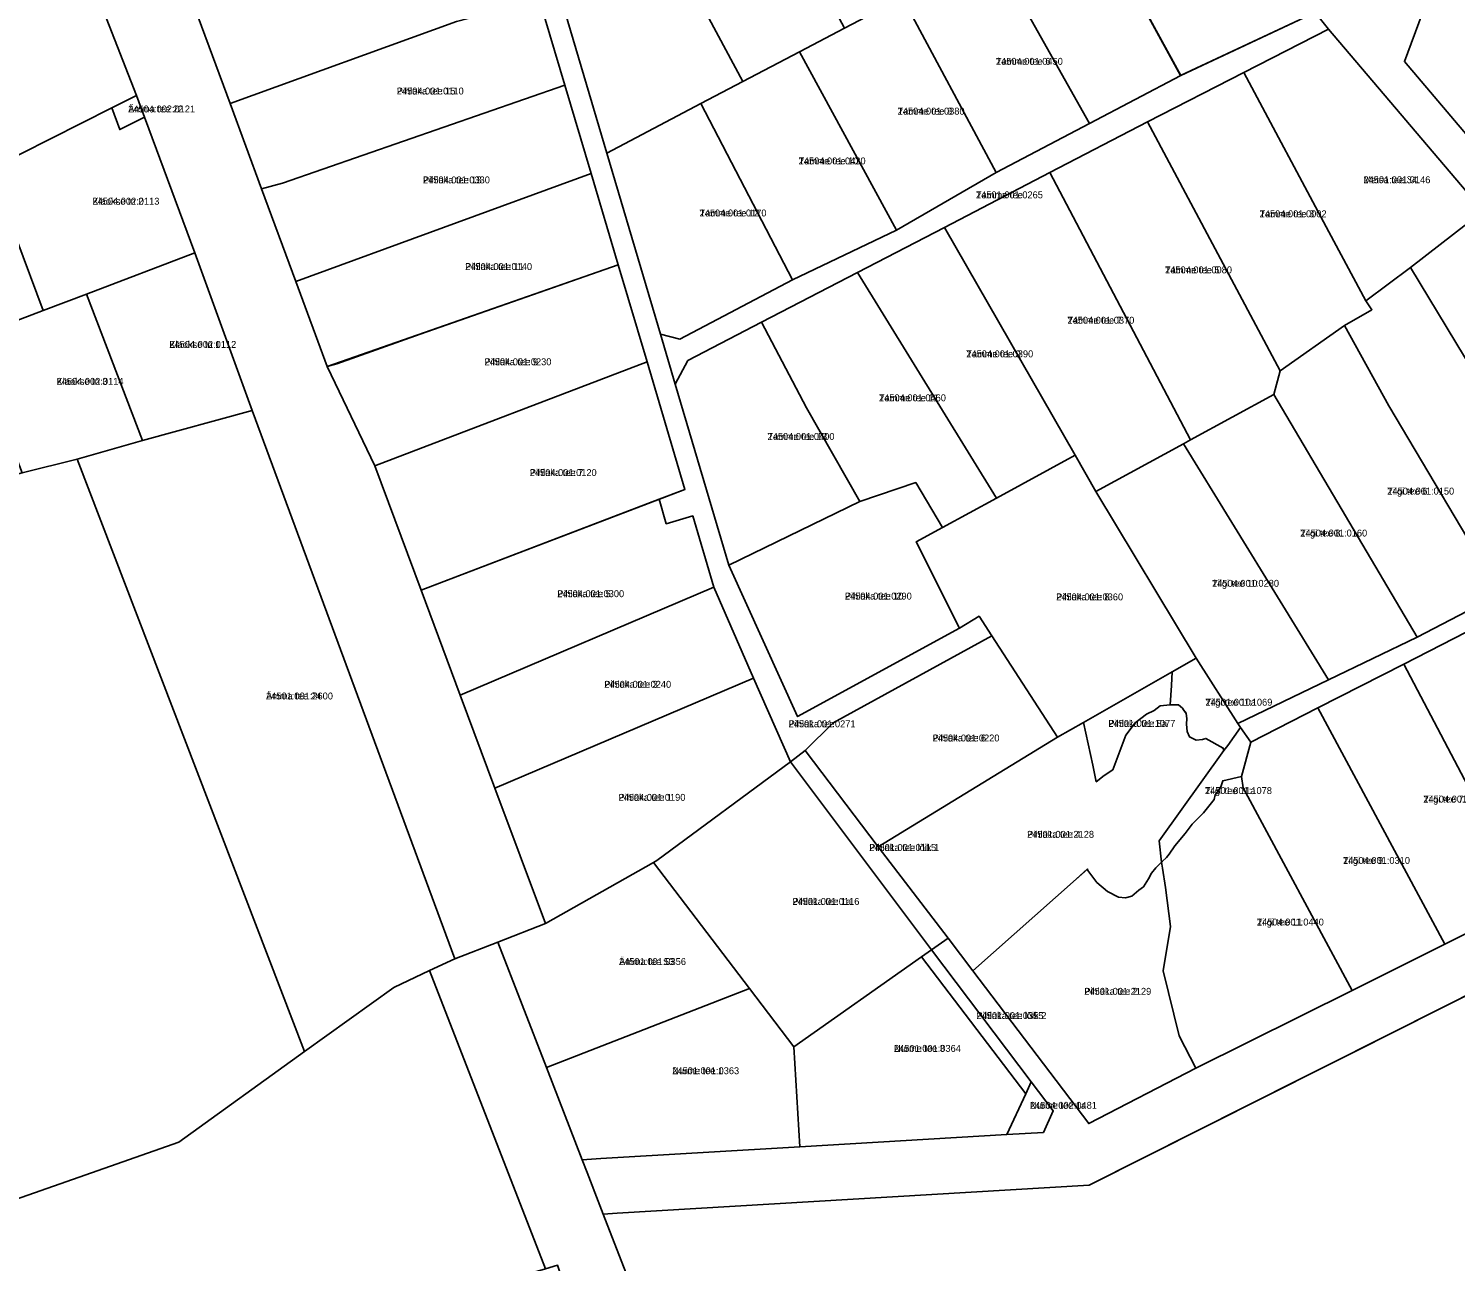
# Model space of a CAD drawing. Extents: x 551291 to 575799, y 6581704 to 6610137.
# Drawn here: x 551707.6 to 552016.8, y 6590972.2 to 6591239.3 of the extents above; entities that cross this region are included whole.
import ezdxf

# ---------------------------------------------------------------- set-up
doc = ezdxf.new("R2010")
doc.units = 0
for name, color, linetype in [('L_AADRESS', 7, 'Continuous'), ('PIIR', 7, 'Continuous'), ('TUNNUS', 7, 'Continuous')]:
    doc.layers.add(name, color=color, linetype=linetype)

msp = doc.modelspace()

# ---------------------------------------------------------------- linework, layer by layer
at = {"layer": 'PIIR'}
for points in [[(551701.29, 6591351.43), (551712.87, 6591319.4), (551715.45, 6591320.33), (551724.64, 6591295.4), (551734.51, 6591268.62), (551744.41, 6591241.79), (551751.32, 6591223.06), (551758.13, 6591204.61), (551765.54, 6591184.52), (551772.34, 6591166.09), (551782.64, 6591144.59), (551792.69, 6591117.63), (551801.16, 6591094.92), (551808.64, 6591074.74), (551819.62, 6591045.45), (551809.29, 6591041.41), (551800.02, 6591037.82), (551756.11, 6591156.6), (551743.63, 6591190.71), (551732.76, 6591220.16), (551731.03, 6591224.85), (551697.08, 6591311.6)], [(551821.21, 6591251.88), (551832.93, 6591212.34), (551844.57, 6591173.08), (551847.77, 6591162.31), (551859.38, 6591123.09), (551874.27, 6591090.27), (551909.33, 6591109.44), (551913.61, 6591112.01), (551916.35, 6591107.73), (551881.97, 6591088.88), (551875.88, 6591082.91), (551872.7, 6591080.47), (551864.73, 6591098.59), (551856.15, 6591118.28), (551851.55, 6591133.75), (551845.8, 6591132.04), (551844.24, 6591137.36), (551849.84, 6591139.5), (551841.64, 6591167.12), (551835.39, 6591188.16), (551829.52, 6591207.93), (551823.84, 6591227.04), (551818.36, 6591245.46)], [(552041.41, 6591041.02), (551994.68, 6591017.51), (551983.25, 6591011.76), (551937.47, 6590988.73), (551835.16, 6590982.69), (551832.17, 6590982.51), (551831.44, 6590984.38), (551828.69, 6590991.47), (551827.6, 6590994.26), (551831.6, 6590994.5), (551874.74, 6590997.05), (551919.58, 6590999.71), (551927.52, 6591000.16), (551929.68, 6591004.83), (551924.89, 6591011.17), (551903.3, 6591039.74), (551906.87, 6591042.28), (551912.23, 6591035.19), (551937.34, 6591002.11), (551960.57, 6591014.09), (551994.47, 6591030.95), (552014.5, 6591041), (552032.69, 6591050.15)]]:
    msp.add_lwpolyline(points, dxfattribs=at)
for points in [[(551592.26, 6591318.17), (551621.99, 6591332.29), (551623.99, 6591329.04), (551632.52, 6591311.28), (551638.82, 6591301.29), (551648.47, 6591293.24), (551660.58, 6591291.58), (551671.63, 6591296.03), (551697.08, 6591311.6), (551731.03, 6591224.85), (551725.67, 6591222.15), (551699.31, 6591208.85), (551670.73, 6591194.44), (551633.68, 6591175.75), (551582.09, 6591146.82), (551586.14, 6591107.57), (551562.34, 6591100.09), (551552.1, 6591119.71), (551549.82, 6591157.52), (551565.91, 6591305.65), (551578.48, 6591311.61)], [(552005.77, 6591232.17), (552015.83, 6591259.33), (552088.53, 6591298.69), (552112.37, 6591206.21), (552049.91, 6591174.23), (552042.31, 6591189.1)], [(551744.41, 6591241.79), (551781.76, 6591257.73), (551796, 6591268.19), (551802.72, 6591274.63), (551806.37, 6591277.83), (551819.04, 6591259.7), (551817.04, 6591252.23), (551818.36, 6591245.46), (551800.32, 6591240.84), (551751.32, 6591223.06)], [(551841.89, 6591266.09), (551864.01, 6591277.78), (551884.41, 6591239.44), (551874.65, 6591234.3), (551862.38, 6591227.84)], [(551936.63, 6591266.94), (551956.64, 6591277.45), (551986.13, 6591243.2), (551986.45, 6591242.8), (551957.26, 6591229.16)], [(551821.21, 6591251.88), (551822.78, 6591256), (551841.89, 6591266.09), (551862.38, 6591227.84), (551853.31, 6591223.07), (551832.93, 6591212.34)], [(551928.43, 6591262.61), (551936.66, 6591266.94), (551957.29, 6591229.16), (551937.5, 6591218.74), (551916.4, 6591256.28)], [(551986.45, 6591242.8), (551986.13, 6591243.2), (552010.61, 6591256.5), (552015.83, 6591259.33), (552005.77, 6591232.17), (552042.31, 6591189.1), (552049.91, 6591174.23), (552072.65, 6591129.71), (552065.53, 6591126.08), (552063.05, 6591130.94), (552061.12, 6591134.72), (552035.62, 6591184.65), (552022.81, 6591199.75), (551989.34, 6591239.21)], [(551906.25, 6591250.94), (551916.4, 6591256.28), (551937.5, 6591218.74), (551917.26, 6591208.12), (551896.98, 6591246.06)], [(551800.32, 6591240.84), (551818.36, 6591245.46), (551823.84, 6591227.04), (551762.65, 6591205.81), (551758.13, 6591204.61), (551751.32, 6591223.06)], [(551874.65, 6591234.3), (551884.41, 6591239.44), (551896.98, 6591246.06), (551917.26, 6591208.12), (551895.69, 6591195.68)], [(551986.45, 6591242.8), (551989.34, 6591239.21), (551970.94, 6591229.81), (551950.07, 6591219.1), (551928.94, 6591208.12), (551906.07, 6591196.24), (551887.24, 6591186.46), (551866.46, 6591175.69), (551850.49, 6591167.41), (551847.77, 6591162.31), (551844.57, 6591173.08), (551848.73, 6591172.06), (551873.13, 6591184.9), (551895.69, 6591195.68), (551917.26, 6591208.12), (551937.5, 6591218.74), (551957.29, 6591229.16)], [(551970.94, 6591229.81), (551989.34, 6591239.21), (552022.81, 6591199.75), (552007.11, 6591187.53), (551997.39, 6591180.36), (551989.4, 6591195.28)], [(551862.38, 6591227.84), (551874.65, 6591234.3), (551895.69, 6591195.68), (551873.13, 6591184.9), (551853.31, 6591223.07)], [(551970.94, 6591229.81), (551989.4, 6591195.28), (551997.39, 6591180.36), (551998.71, 6591178.42), (551992.78, 6591174.99), (551978.84, 6591165.19), (551950.07, 6591219.1)], [(551758.13, 6591204.61), (551762.65, 6591205.81), (551823.84, 6591227.04), (551829.52, 6591207.93), (551765.54, 6591184.52)], [(551725.67, 6591222.15), (551731.03, 6591224.85), (551732.76, 6591220.16), (551727.38, 6591217.45)], [(551853.31, 6591223.07), (551873.13, 6591184.9), (551848.73, 6591172.06), (551844.57, 6591173.08), (551832.93, 6591212.34)], [(551699.31, 6591208.85), (551725.67, 6591222.15), (551727.38, 6591217.45), (551732.76, 6591220.16), (551743.63, 6591190.71), (551720.15, 6591181.8), (551710.76, 6591178.24)], [(551950.07, 6591219.1), (551978.84, 6591165.19), (551977.46, 6591160.07), (551959.38, 6591150.2), (551928.94, 6591208.12)], [(551670.73, 6591194.44), (551699.31, 6591208.85), (551710.76, 6591178.24), (551695.02, 6591172.27), (551681, 6591166.95)], [(551829.52, 6591207.93), (551835.39, 6591188.16), (551792.49, 6591173.14), (551774.39, 6591166.71), (551772.34, 6591166.09), (551765.54, 6591184.52)], [(551957.88, 6591149.38), (551938.87, 6591139), (551934.41, 6591146.9), (551906.07, 6591196.24), (551928.94, 6591208.12), (551959.38, 6591150.2)], [(552022.81, 6591199.75), (552035.58, 6591184.65), (552061.12, 6591134.72), (552044.26, 6591126.06), (552007.11, 6591187.53)], [(551934.41, 6591146.9), (551917.37, 6591137.62), (551887.24, 6591186.46), (551906.07, 6591196.24)], [(551720.15, 6591181.8), (551743.63, 6591190.71), (551756.11, 6591156.6), (551732.35, 6591150.09)], [(551772.34, 6591166.09), (551835.39, 6591188.16), (551841.64, 6591167.12), (551782.64, 6591144.59)], [(551887.24, 6591186.46), (551917.37, 6591137.62), (551905.68, 6591131.26), (551899.87, 6591140.98), (551887.73, 6591136.87), (551876.21, 6591157.13), (551866.46, 6591175.69)], [(551992.78, 6591174.99), (551998.71, 6591178.42), (551997.39, 6591180.36), (552007.11, 6591187.53), (552044.26, 6591126.06), (552026.61, 6591116.88), (552002.4, 6591157.62)], [(551706.24, 6591143.05), (551695.02, 6591172.27), (551710.76, 6591178.24), (551720.15, 6591181.8), (551732.35, 6591150.09), (551718.14, 6591146.05)], [(551847.77, 6591162.31), (551850.49, 6591167.41), (551866.46, 6591175.69), (551876.21, 6591157.13), (551887.73, 6591136.87), (551859.38, 6591123.09)], [(551978.84, 6591165.19), (551992.78, 6591174.99), (552002.4, 6591157.62), (552026.61, 6591116.88), (552008.49, 6591107.5), (551977.46, 6591160.07)], [(551841.64, 6591167.12), (551849.84, 6591139.5), (551792.69, 6591117.63), (551782.64, 6591144.59)], [(551959.38, 6591150.2), (551977.46, 6591160.07), (552008.49, 6591107.5), (551989.3, 6591098.24), (551957.88, 6591149.38)], [(551767.4, 6591017.71), (551718.14, 6591146.05), (551732.35, 6591150.09), (551756.11, 6591156.6), (551800.02, 6591037.82), (551794.54, 6591035.23), (551786.76, 6591031.59)], [(551969.66, 6591088.77), (551960.61, 6591102.94), (551938.87, 6591139), (551957.88, 6591149.38), (551989.3, 6591098.24)], [(551568.89, 6591090.56), (551562.34, 6591100.09), (551586.14, 6591107.57), (551638.15, 6591124.7), (551676.44, 6591134.9), (551706.24, 6591143.05), (551718.14, 6591146.05), (551767.4, 6591017.71), (551740.16, 6590998.04), (551718.56, 6590990.49), (551690.68, 6590980.77), (551688.64, 6590987.27), (551678.52, 6591009.23), (551660.89, 6591023.42), (551605.18, 6591058.47)], [(551905.68, 6591131.26), (551917.37, 6591137.62), (551934.41, 6591146.9), (551938.87, 6591139), (551960.61, 6591102.94), (551955.45, 6591099.93), (551936.25, 6591088.99), (551930.6, 6591085.78), (551916.35, 6591107.73), (551913.61, 6591112.01), (551909.33, 6591109.44), (551899.99, 6591128.16)], [(551887.73, 6591136.87), (551899.87, 6591140.98), (551905.68, 6591131.26), (551899.99, 6591128.16), (551909.33, 6591109.44), (551874.27, 6591090.27), (551859.38, 6591123.09)], [(551792.69, 6591117.63), (551844.24, 6591137.36), (551845.8, 6591132.04), (551851.55, 6591133.75), (551856.15, 6591118.28), (551801.16, 6591094.92)], [(552061.12, 6591134.72), (552063.05, 6591130.94), (552042.3, 6591120.38), (552024.6, 6591111.34), (552005.65, 6591101.66), (551987.03, 6591092.17), (551972.46, 6591084.75), (551970.25, 6591087.91), (551969.66, 6591088.77), (551989.3, 6591098.24), (552008.49, 6591107.5), (552026.61, 6591116.88), (552044.26, 6591126.06)], [(551864.73, 6591098.59), (551808.64, 6591074.74), (551801.16, 6591094.92), (551856.15, 6591118.28)], [(552024.6, 6591111.34), (552053.16, 6591060.44), (552032.69, 6591050.15), (552005.65, 6591101.66)], [(551875.88, 6591082.91), (551881.97, 6591088.88), (551916.35, 6591107.73), (551930.6, 6591085.78), (551891.7, 6591062.04)], [(551961.98, 6591085.28), (551960.64, 6591085.18), (551959.21, 6591085.86), (551958.69, 6591087.04), (551958.53, 6591088.64), (551958.58, 6591089.85), (551958.49, 6591090.97), (551957.92, 6591091.72), (551957.64, 6591092.1), (551956.83, 6591092.82), (551955.03, 6591092.82), (551955.3, 6591097.03), (551955.45, 6591099.93), (551960.61, 6591102.94), (551969.66, 6591088.77), (551970.25, 6591087.91), (551967.46, 6591084.03), (551966.66, 6591082.9), (551966.5, 6591083.43), (551962.74, 6591085.54)], [(551945.41, 6591086.24), (551942.54, 6591078.75), (551940.71, 6591077.53), (551938.98, 6591076.14), (551938.22, 6591079.71), (551936.25, 6591088.99), (551955.45, 6591099.93), (551955.3, 6591097.03), (551955.03, 6591092.82), (551952.81, 6591092.59), (551951.5, 6591091.6), (551949.9, 6591090.81), (551947.43, 6591088.9)], [(552014.5, 6591041), (551987.03, 6591092.17), (552005.65, 6591101.66), (552032.69, 6591050.15)], [(551819.62, 6591045.45), (551808.64, 6591074.74), (551864.73, 6591098.59), (551872.7, 6591080.47), (551843.78, 6591059.11), (551843.01, 6591058.64)], [(551906.87, 6591042.28), (551891.7, 6591062.04), (551930.6, 6591085.78), (551936.25, 6591088.99), (551938.22, 6591079.71), (551938.98, 6591076.14), (551940.71, 6591077.53), (551942.54, 6591078.75), (551945.41, 6591086.24), (551947.43, 6591088.9), (551949.9, 6591090.81), (551951.5, 6591091.6), (551952.81, 6591092.59), (551955.03, 6591092.82), (551956.83, 6591092.82), (551957.64, 6591092.1), (551957.92, 6591091.72), (551958.49, 6591090.98), (551958.58, 6591089.85), (551958.53, 6591088.64), (551958.69, 6591087.04), (551959.21, 6591085.85), (551960.64, 6591085.18), (551961.98, 6591085.28), (551962.74, 6591085.54), (551966.5, 6591083.43), (551966.66, 6591082.9), (551952.63, 6591063.37), (551953.13, 6591058.71), (551951.92, 6591057.52), (551950.98, 6591056.36), (551950.31, 6591055.12), (551949.22, 6591053.39), (551948.2, 6591052.63), (551946.71, 6591051.38), (551945.34, 6591050.97), (551943.8, 6591051.15), (551941.45, 6591052.36), (551939.12, 6591054.33), (551937.14, 6591056.89), (551937.08, 6591057.26), (551934.6, 6591055.05), (551912.23, 6591035.19)], [(551970.43, 6591077.27), (551972.46, 6591084.75), (551987.03, 6591092.17), (552014.5, 6591041), (551994.47, 6591030.95), (551970.83, 6591074.86)], [(551954.21, 6591059.76), (551953.28, 6591058.85), (551953.24, 6591058.82), (551953.13, 6591058.71), (551952.63, 6591063.37), (551966.66, 6591082.9), (551967.46, 6591084.03), (551970.25, 6591087.91), (551972.46, 6591084.75), (551970.43, 6591077.27), (551966.41, 6591076.36), (551965.95, 6591075.03), (551965.28, 6591073.99), (551964.74, 6591073.32), (551964.56, 6591072.33), (551962.23, 6591069.39), (551959.75, 6591066.99), (551958.22, 6591064.93), (551956.01, 6591062.28), (551954.75, 6591060.44)], [(551843.78, 6591059.11), (551872.7, 6591080.47), (551903.3, 6591039.74), (551901.15, 6591038.23), (551873.44, 6591018.71), (551863.83, 6591031.34), (551843.01, 6591058.64)], [(551872.7, 6591080.47), (551875.88, 6591082.91), (551891.7, 6591062.04), (551906.87, 6591042.28), (551903.3, 6591039.74)], [(551970.83, 6591074.86), (551994.47, 6591030.95), (551960.57, 6591014.09), (551956.96, 6591021.08), (551953.51, 6591035.17), (551955.04, 6591044.76), (551953.96, 6591053.25), (551953.35, 6591057.4), (551953.13, 6591058.71), (551953.24, 6591058.82), (551953.28, 6591058.85), (551954.21, 6591059.76), (551954.75, 6591060.44), (551956.01, 6591062.28), (551958.22, 6591064.93), (551959.75, 6591066.99), (551962.23, 6591069.39), (551964.56, 6591072.33), (551964.74, 6591073.32), (551965.28, 6591073.99), (551965.95, 6591075.03), (551966.41, 6591076.36), (551970.43, 6591077.27)], [(551819.84, 6591014.26), (551809.29, 6591041.41), (551819.62, 6591045.45), (551843.01, 6591058.64), (551863.83, 6591031.34)], [(551953.13, 6591058.71), (551953.35, 6591057.4), (551953.96, 6591053.25), (551955.04, 6591044.76), (551953.51, 6591035.17), (551956.96, 6591021.08), (551960.57, 6591014.09), (551937.34, 6591002.11), (551912.23, 6591035.19), (551934.6, 6591055.05), (551937.08, 6591057.25), (551937.14, 6591056.89), (551939.12, 6591054.33), (551941.45, 6591052.36), (551943.8, 6591051.15), (551945.34, 6591050.97), (551946.71, 6591051.38), (551948.2, 6591052.63), (551949.22, 6591053.39), (551950.31, 6591055.12), (551950.98, 6591056.36), (551951.92, 6591057.52)], [(551832.17, 6590982.51), (551835.16, 6590982.69), (551937.47, 6590988.73), (552052.66, 6591046.68), (552056.48, 6591022.45), (552064.27, 6590973.05), (552072.83, 6590918.72), (552081.4, 6590864.38), (552088.59, 6590818.77), (552089.5, 6590812.94), (551918.6, 6590788.49), (551886.69, 6590842.14)], [(551794.54, 6591035.23), (551800.02, 6591037.82), (551809.29, 6591041.41), (551819.84, 6591014.26), (551827.6, 6590994.26), (551828.69, 6590991.47), (551831.44, 6590984.38), (551832.17, 6590982.51), (551886.69, 6590842.14), (551918.6, 6590788.49), (551924.85, 6590777.97), (551903.02, 6590774.88), (551901.43, 6590786.05), (551889.25, 6590806.53), (551872.82, 6590834.16), (551872.26, 6590835.1), (551869, 6590843.49), (551856.98, 6590874.44), (551847.31, 6590899.33), (551837.58, 6590924.39), (551822.99, 6590961.96), (551825.13, 6590962.55), (551822.27, 6590971.41), (551819.61, 6590970.63)], [(551874.74, 6590997.05), (551873.44, 6591018.71), (551901.15, 6591038.23), (551923.7, 6591008.56), (551919.58, 6590999.71)], [(551923.7, 6591008.56), (551901.15, 6591038.23), (551903.3, 6591039.74), (551924.91, 6591011.16)], [(551698.09, 6590955.05), (551690.68, 6590980.77), (551718.56, 6590990.49), (551740.16, 6590998.04), (551767.4, 6591017.71), (551786.76, 6591031.59), (551794.54, 6591035.23), (551819.61, 6590970.63), (551815.16, 6590969.32), (551797.8, 6590962.57), (551787.92, 6590905.1), (551782.6, 6590874.19), (551777.32, 6590843.5), (551770.75, 6590805.28), (551767.78, 6590787.98), (551772.28, 6590756.35), (551710.96, 6590747.66), (551655.02, 6590739.72), (551623.91, 6590735.04), (551640.06, 6590768.98), (551673.7, 6590805.26), (551693.9, 6590853.77), (551696.13, 6590876.83)], [(551827.6, 6590994.26), (551819.84, 6591014.26), (551863.83, 6591031.34), (551873.44, 6591018.71), (551874.74, 6590997.05), (551831.6, 6590994.5)], [(551919.58, 6590999.71), (551923.7, 6591008.56), (551924.89, 6591011.17), (551929.68, 6591004.83), (551927.52, 6591000.16)]]:
    msp.add_lwpolyline(points, close=True, dxfattribs=at)

# ---------------------------------------------------------------- texts
at = {"layer": 'L_AADRESS'}
for s, p in [('Tamme tee 6', (551917.24, 6591231.47)), ('Pihlaka tee 15', (551787.41, 6591225.04)), ('Ämma tee 22', (551729.21, 6591221.15)), ('Tamme tee 8', (551895.95, 6591220.68)), ('Tamme tee 10', (551874.5, 6591209.89)), ('Pihlaka tee 13', (551793.09, 6591205.78)), ('Metsa tee 34', (551996.88, 6591205.82)), ('Tamme tee', (551912.92, 6591202.55)), ('Klaokse tn 2', (551721.47, 6591201.17)), ('Tamme tee 12', (551853.03, 6591198.62)), ('Tamme tee 3', (551974.39, 6591198.44)), ('Pihlaka tee 11', (551802.23, 6591187.01)), ('Tamme tee 5', (551953.89, 6591186.29)), ('Tamme tee 7', (551932.73, 6591175.38)), ('Klaokse tn 1', (551738.13, 6591170.15)), ('Pihlaka tee 9', (551806.42, 6591166.38)), ('Tamme tee 9', (551910.82, 6591168.1)), ('Klaokse tn 3', (551713.69, 6591162.14)), ('Tamme tee 11', (551891.91, 6591158.58)), ('Tamme tee 13', (551867.75, 6591150.2)), ('Pihlaka tee 7', (551816.23, 6591142.38)), ('Tiigi tee 6', (552002.04, 6591138.36)), ('Tiigi tee 8', (551983.19, 6591129.28)), ('Pihlaka tee 5', (551822.18, 6591116.14)), ('Tiigi tee 10', (551964.08, 6591118.39)), ('Pihlaka tee 10', (551884.51, 6591115.62)), ('Pihlaka tee 8', (551930.3, 6591115.45)), ('Ämma tee 24', (551759.08, 6591093.98)), ('Pihlaka tee 3', (551832.37, 6591096.51)), ('Tiigi tee 10a', (551962.64, 6591092.63)), ('Pihlaka tee', (551872.32, 6591087.95)), ('Pihlaka tee 8a', (551941.61, 6591088.04)), ('Pihlaka tee 6', (551903.51, 6591084.88)), ('Tiigi tee 11a', (551962.55, 6591073.48)), ('Pihlaka tee 1', (551835.46, 6591072.02)), ('Tiigi tee 7', (552009.86, 6591071.64)), ('Pihlaka tee 4', (551924, 6591064.01)), ('Pihlaka tee lõik 1', (551889.79, 6591061.15)), ('Tiigi tee 9', (551992.46, 6591058.36)), ('Pihlaka tee 1a', (551873.15, 6591049.47)), ('Tiigi tee 11', (551973.8, 6591045.01)), ('Ämma tee 53', (551835.58, 6591036.45)), ('Pihlaka tee 2', (551936.4, 6591030)), ('Pihlaka tee lõik 2', (551913.03, 6591024.74)), ('Nurme tee 3', (551895.15, 6591017.64)), ('Nurme tee 1', (551847.1, 6591012.8)), ('Nurme tee 1a', (551924.63, 6591005.3))]:
    msp.add_text(s, height=1.5, dxfattribs=at).set_placement(p)
at = {"layer": 'TUNNUS'}
for s, p in [('24504:001:0450', (551917.24, 6591231.47)), ('24504:001:0110', (551787.41, 6591225.04)), ('24504:002:0121', (551729.21, 6591221.15)), ('24504:001:0380', (551895.95, 6591220.68)), ('24504:001:0430', (551874.5, 6591209.89)), ('24504:001:0330', (551793.09, 6591205.78)), ('24501:001:0146', (551996.88, 6591205.82)), ('24501:001:0265', (551912.92, 6591202.55)), ('24504:002:0113', (551721.47, 6591201.17)), ('24504:001:0170', (551853.03, 6591198.62)), ('24504:001:0002', (551974.39, 6591198.44)), ('24504:001:0140', (551802.23, 6591187.01)), ('24504:001:0080', (551953.89, 6591186.29)), ('24504:001:0370', (551932.73, 6591175.38)), ('24504:002:0112', (551738.13, 6591170.15)), ('24504:001:0230', (551806.42, 6591166.38)), ('24504:001:0390', (551910.82, 6591168.1)), ('24504:002:0114', (551713.69, 6591162.14)), ('24504:001:0460', (551891.91, 6591158.58)), ('24504:001:0400', (551867.75, 6591150.2)), ('24504:001:0120', (551816.23, 6591142.38)), ('24504:001:0150', (552002.04, 6591138.36)), ('24504:001:0160', (551983.19, 6591129.28)), ('24504:001:0300', (551822.18, 6591116.14)), ('24504:001:0280', (551964.08, 6591118.39)), ('24504:001:0290', (551884.51, 6591115.62)), ('24504:001:0360', (551930.3, 6591115.45)), ('24504:001:0240', (551832.37, 6591096.51)), ('24501:001:2600', (551759.08, 6591093.98)), ('24501:001:1069', (551962.64, 6591092.63)), ('24501:001:1077', (551941.61, 6591088.04)), ('24501:001:0271', (551872.32, 6591087.95)), ('24504:001:0220', (551903.51, 6591084.88)), ('24501:001:1078', (551962.55, 6591073.48)), ('24504:001:0190', (551835.46, 6591072.02)), ('24504:001:0260', (552009.86, 6591071.64)), ('24501:001:2128', (551924, 6591064.01)), ('24501:001:0115', (551889.79, 6591061.15)), ('24504:001:0310', (551992.46, 6591058.36)), ('24501:001:0116', (551873.15, 6591049.47)), ('24504:001:0440', (551973.8, 6591045.01)), ('24501:001:0356', (551835.58, 6591036.45)), ('24501:001:2129', (551936.4, 6591030)), ('24501:001:0355', (551913.03, 6591024.74)), ('24501:001:0364', (551895.15, 6591017.64)), ('24501:001:0363', (551847.1, 6591012.8)), ('24504:002:0481', (551924.63, 6591005.3))]:
    msp.add_text(s, height=1.5, dxfattribs=at).set_placement(p)

doc.saveas('drawing.dxf')
